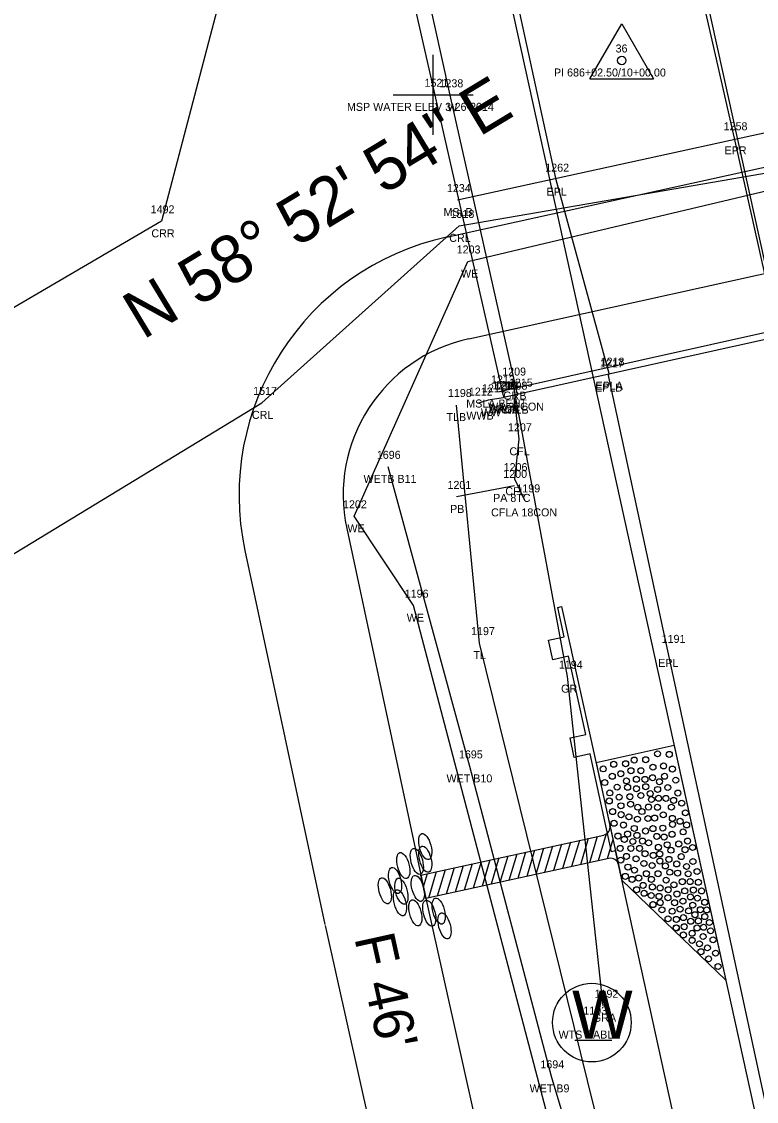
# Model space of a CAD drawing. Extents: x 2521558 to 2525396, y 882711 to 887632.
# Drawn here: x 2523714.7 to 2523806.5, y 884989.6 to 885124.5 of the extents above; entities that cross this region are included whole.
import ezdxf

# ---------------------------------------------------------------- set-up
doc = ezdxf.new("R2010")
doc.units = 0
for name, color, linetype in [('RD_EV_JurisArea', 7, 'Continuous'), ('RD_EX_BldgApp', 7, 'Continuous'), ('RD_EX_BldgApp_txCode', 7, 'Continuous'), ('RD_EX_Bridge', 7, 'Continuous'), ('RD_EX_Bridge_txCode', 7, 'Continuous'), ('RD_EX_Conc', 7, 'Continuous'), ('RD_EX_Conc_txCode', 7, 'Continuous'), ('RD_EX_DR_Pipe', 7, 'Continuous'), ('RD_EX_DR_Pipe_txCode', 7, 'Continuous'), ('RD_EX_GuardRail', 7, 'Continuous'), ('RD_EX_GuardRail_txCode', 7, 'Continuous'), ('RD_EX_H2O', 7, 'Continuous'), ('RD_EX_H2O_txCode', 7, 'Continuous'), ('RD_EX_H2O_WetLd_txCode', 7, 'Continuous'), ('RD_EX_Misc', 7, 'Continuous'), ('RD_EX_Misc_txCode', 7, 'Continuous'), ('RD_EX_Road', 7, 'Continuous'), ('RD_EX_Road_txCode', 7, 'Continuous'), ('RD_EX_UT', 7, 'Continuous'), ('RD_EX_UT_txCode', 7, 'Continuous'), ('RD_EX_VEG', 7, 'Continuous'), ('RD_EX_VEG_txCode', 7, 'Continuous'), ('RD_HC_Data', 7, 'Continuous'), ('RD_HC_txCode', 7, 'Continuous'), ('RD_PD_Bridge', 7, 'Continuous'), ('RD_PD_CstnLmt', 7, 'Continuous'), ('RD_PD_DR_ErosCtrl', 7, 'Continuous'), ('RD_PD_Final_TrvlWay', 7, 'Continuous'), ('RD_PD_GR', 7, 'Continuous'), ('RD_PD_PaveShd', 7, 'Continuous'), ('RD_SMD_Locator', 7, 'Continuous')]:
    doc.layers.add(name, color=color, linetype=linetype)

# ---------------------------------------------------------------- blocks, each defined once
blk = doc.blocks.new('TBC1')
at = {"layer": 'RD_PD_GR'}
blk.add_lwpolyline([(12.5, 2.5), (15, 2.5), (15, 0.49), (25, 0.49), (25, 2.5), (27.5, 2.5), (27.5, 0.49), (31.25, 0.49), (31.25, 0), (0, 0), (0, 0.49), (12.5, 0.49)], close=True, dxfattribs=at)

msp = doc.modelspace()

# ---------------------------------------------------------------- linework, layer by layer
at = {"layer": 'RD_EV_JurisArea'}
msp.add_lwpolyline([(2523827.75, 884469.64), (2523867.43, 884517.67), (2523885.95, 884534.84), (2523882.77, 884582.72), (2523847.74, 884736.42), (2523822.93, 884833.79), (2523804.26, 884914.89), (2523780.91, 884992.76), (2523770.73, 885031.48), (2523760.5, 885068.9)], dxfattribs=at)
at = {"layer": 'RD_EX_BldgApp'}
msp.add_lwpolyline([(2523776.68, 885077.92), (2523768.27, 885115.31), (2523760.2, 885151.9)], dxfattribs=at)
at = {"layer": 'RD_EX_Bridge'}
for points in [[(2523774.91, 885077.6), (2523821.2, 885087.83), (2523805.06, 885161.89), (2523758.15, 885151.44), (2523774.91, 885077.6)], [(2523774.9, 885077.54), (2523773.02, 885077.21), (2523771.67, 885076.8)]]:
    msp.add_lwpolyline(points, dxfattribs=at)
at = {"layer": 'RD_EX_Conc'}
msp.add_lwpolyline([(2523777.61, 885064.71), (2523776.36, 885067.36), (2523776.88, 885072.34), (2523776.32, 885077.54)], dxfattribs=at)
at = {"layer": 'RD_EX_DR_Pipe'}
msp.add_line((2523776.32, 885066.52), (2523769.04, 885065.14), dxfattribs=at)
at = {"layer": 'RD_EX_GuardRail'}
msp.add_lwpolyline([(2523787.38, 885001.58), (2523782.91, 885042.69), (2523776.15, 885079.3)], dxfattribs=at)
at = {"layer": 'RD_EX_H2O'}
for points in [[(2523582.82, 884766.34), (2523598.11, 884856.98), (2523627.59, 884901.75), (2523623.76, 884928.28), (2523586.58, 884955.43), (2523600.94, 884974.12), (2523633.05, 884997.68), (2523679.17, 885037.05), (2523744.72, 885076.89), (2523769.38, 885099), (2523825.47, 885108.66), (2523825.47, 885108.66), (2523845.24, 885110.83), (2523890.25, 885154.93)], [(2523741.75, 885135.92), (2523732.18, 885099.57), (2523664.9, 885060.26), (2523614.86, 885022.02), (2523558.95, 884972.63), (2523560.62, 884942.42), (2523490.01, 884911.76)], [(2523792.73, 884941.12), (2523763.67, 885051.56), (2523756.26, 885062.72), (2523770.47, 885094.55), (2523817.57, 885105.71), (2523827.83, 885106)]]:
    msp.add_lwpolyline(points, dxfattribs=at)
at = {"layer": 'RD_EX_Misc'}
for p, q in [((2523766.13, 885110.37), (2523766.13, 885120.37)), ((2523761.13, 885115.37), (2523771.13, 885115.37)), ((2523816.08, 885112.47), (2523769.2, 885102.22)), ((2523774.43, 885078.31), (2523821.35, 885088.78))]:
    msp.add_line(p, q, dxfattribs=at)
at = {"layer": 'RD_EX_Road'}
for p, q in [((2523803.79, 885109.94), (2523798.3, 885134.14)), ((2523781.52, 885104.77), (2523776.18, 885129.21)), ((2523809.32, 885085.19), (2523803.79, 885109.94)), ((2523788.14, 885080.54), (2523781.52, 885104.77)), ((2523788.05, 885080.31), (2523788.14, 885080.54)), ((2523795.47, 885045.91), (2523788.05, 885080.31)), ((2523817, 884946.3), (2523795.47, 885045.91))]:
    msp.add_line(p, q, dxfattribs=at)
at = {"layer": 'RD_EX_UT'}
msp.add_line((2523783.84, 884997.27), (2523788.47, 884997.27), dxfattribs=at)
msp.add_circle((2523785.97, 884999.48), 4.91, dxfattribs=at)
at = {"layer": 'RD_EX_VEG'}
msp.add_lwpolyline([(2523800.23, 884418.22), (2523892.24, 884498.97), (2523844.57, 884752.81), (2523771.94, 885046.88), (2523769.06, 885076.62)], dxfattribs=at)
at = {"layer": 'RD_HC_Data'}
for p, q in [((2523785.73, 885117.37), (2523789.7, 885124.25)), ((2523789.7, 885124.25), (2523793.67, 885117.37)), ((2523785.73, 885117.37), (2523793.67, 885117.37))]:
    msp.add_line(p, q, dxfattribs=at)
msp.add_circle((2523789.7, 885119.66), 0.529, dxfattribs=at)
at = {"layer": 'RD_PD_CstnLmt'}
for p, q in [((2523755.34, 885061.18), (2523765.33, 885014.45)), ((2523765.33, 885014.45), (2523787.17, 884916.87))]:
    msp.add_line(p, q, dxfattribs=at)
msp.add_lwpolyline([(2523770.59, 885084.9), (2523821.14, 885096.03)], dxfattribs=at)
msp.add_arc((2523774.89, 885065.36), 20, 102.4185, 192.0677, dxfattribs=at)
at = {"layer": 'RD_PD_DR_ErosCtrl'}
for p, q in [((2523742.62, 885058.46), (2523752.61, 885011.74)), ((2523752.64, 885011.61), (2523774.49, 884914.03))]:
    msp.add_line(p, q, dxfattribs=at)
msp.add_lwpolyline([(2523767.8, 885097.59), (2523818.34, 885108.72)], dxfattribs=at)
msp.add_arc((2523774.89, 885065.36), 33, 102.4185, 192.0677, dxfattribs=at)
at = {"layer": 'RD_PD_Final_TrvlWay'}
for p, q in [((2523720.24, 885490.91), (2524037.44, 884050.42)), ((2523696.8, 885485.75), (2524014, 884045.26))]:
    msp.add_line(p, q, dxfattribs=at)
at = {"layer": 'RD_PD_GR'}
msp.add_line((2523896.44, 884532.63), (2523788.91, 885020.93), dxfattribs=at)
at = {"layer": 'RD_PD_PaveShd'}
for p, q in [((2523796.26, 885034.07), (2523786.49, 885031.92)), ((2523796.26, 885034.07), (2523802.71, 885004.77)), ((2523786.49, 885031.92), (2523788.43, 885023.13)), ((2523764.59, 885017.89), (2523787.45, 885022.91)), ((2523784.41, 885022.24), (2523783.42, 885018.96)), ((2523784.41, 885022.24), (2523783.42, 885018.96)), ((2523785.52, 885022.49), (2523784.54, 885019.2)), ((2523785.52, 885022.49), (2523784.54, 885019.2)), ((2523786.64, 885022.74), (2523785.66, 885019.45)), ((2523786.64, 885022.74), (2523785.66, 885019.45)), ((2523787.78, 885023.05), (2523786.77, 885019.69)), ((2523788.61, 885022.33), (2523787.89, 885019.94)), ((2523788.43, 885023.13), (2523789.08, 885020.2)), ((2523777.7, 885020.77), (2523776.72, 885017.48)), ((2523777.7, 885020.77), (2523776.72, 885017.48)), ((2523778.82, 885021.02), (2523777.83, 885017.73)), ((2523778.82, 885021.02), (2523777.83, 885017.73)), ((2523779.94, 885021.26), (2523778.95, 885017.98)), ((2523779.94, 885021.26), (2523778.95, 885017.98)), ((2523781.05, 885021.51), (2523780.07, 885018.22)), ((2523781.05, 885021.51), (2523780.07, 885018.22)), ((2523782.17, 885021.75), (2523781.19, 885018.47)), ((2523782.17, 885021.75), (2523781.19, 885018.47)), ((2523783.29, 885022), (2523782.3, 885018.71)), ((2523788.1, 885019.98), (2523765.22, 885014.96)), ((2523772.12, 885019.55), (2523771.13, 885016.26)), ((2523772.12, 885019.55), (2523771.13, 885016.26)), ((2523773.23, 885019.79), (2523772.25, 885016.5)), ((2523773.23, 885019.79), (2523772.37, 885016.91)), ((2523774.35, 885020.04), (2523773.37, 885016.75)), ((2523774.35, 885020.04), (2523773.37, 885016.75)), ((2523775.47, 885020.28), (2523774.48, 885016.99)), ((2523775.47, 885020.28), (2523774.48, 885016.99)), ((2523776.58, 885020.53), (2523775.6, 885017.24)), ((2523776.58, 885020.53), (2523775.6, 885017.24)), ((2523789.08, 885020.2), (2523789.72, 885017.27)), ((2523765.41, 885018.07), (2523764.91, 885016.4)), ((2523766.53, 885018.32), (2523765.54, 885015.03)), ((2523766.53, 885018.32), (2523765.67, 885015.44)), ((2523767.65, 885018.56), (2523766.66, 885015.28)), ((2523767.65, 885018.56), (2523766.66, 885015.28)), ((2523768.76, 885018.81), (2523767.78, 885015.52)), ((2523768.76, 885018.81), (2523767.78, 885015.52)), ((2523769.88, 885019.05), (2523768.9, 885015.77)), ((2523769.88, 885019.05), (2523768.9, 885015.77)), ((2523771, 885019.3), (2523770.01, 885016.01)), ((2523771, 885019.3), (2523770.01, 885016.01)), ((2523765.22, 885014.96), (2523764.59, 885017.89)), ((2523802.71, 885004.77), (2523789.72, 885017.27))]:
    msp.add_line(p, q, dxfattribs=at)
for centre in [(2523794.18, 885033.05), (2523794.18, 885033.05), (2523795.65, 885032.98), (2523795.65, 885032.98), (2523788.7, 885031.75), (2523788.7, 885031.75), (2523790.19, 885031.82), (2523790.19, 885031.82), (2523791.26, 885032.27), (2523791.26, 885032.27), (2523792.7, 885032.31), (2523792.7, 885032.31), (2523793.61, 885031.38), (2523793.61, 885031.38), (2523794.93, 885031.54), (2523794.93, 885031.54), (2523787.39, 885031.17), (2523787.39, 885031.17), (2523787.39, 885031.17), (2523788.52, 885030.25), (2523788.52, 885030.25), (2523789.59, 885030.57), (2523789.59, 885030.57), (2523790.86, 885030.94), (2523790.86, 885030.94), (2523791.53, 885029.87), (2523791.53, 885029.87), (2523792.1, 885030.94), (2523792.1, 885030.94), (2523792.61, 885029.86), (2523792.61, 885029.86), (2523793.55, 885030.07), (2523793.55, 885030.07), (2523795.05, 885030.24), (2523795.05, 885030.24), (2523796.03, 885031.15), (2523796.03, 885031.15), (2523787.58, 885029.46), (2523787.58, 885029.46), (2523789.13, 885028.89), (2523789.13, 885028.89), (2523790.3, 885029.67), (2523790.3, 885029.67), (2523790.44, 885028.87), (2523790.44, 885028.87), (2523791.55, 885028.69), (2523791.55, 885028.69), (2523792.7, 885028.94), (2523792.7, 885028.94), (2523794.19, 885028.6), (2523794.19, 885028.6), (2523794.42, 885029.57), (2523794.42, 885029.57), (2523795.46, 885028.84), (2523795.46, 885028.84), (2523796.46, 885029.76), (2523796.46, 885029.76), (2523788.15, 885027.16), (2523788.15, 885027.16), (2523788.21, 885028.17), (2523788.21, 885028.17), (2523789.38, 885027.64), (2523789.38, 885027.64), (2523790.72, 885027.69), (2523790.72, 885027.69), (2523792.1, 885027.84), (2523792.1, 885027.84), (2523793.26, 885028.08), (2523793.42, 885027.34), (2523793.42, 885027.34), (2523794.3, 885027.5), (2523794.3, 885027.5), (2523795.22, 885027.48), (2523795.22, 885027.48), (2523796.19, 885027.24), (2523796.19, 885027.24), (2523796.72, 885028.15), (2523796.72, 885028.15), (2523788.57, 885025.83), (2523788.57, 885025.83), (2523789.61, 885026.56), (2523789.61, 885026.56), (2523790.81, 885026.76), (2523790.81, 885026.76), (2523791.71, 885026.38), (2523791.71, 885026.38), (2523792.23, 885025.84), (2523792.23, 885025.84), (2523793.05, 885026.4), (2523793.05, 885026.4), (2523794.17, 885026.37), (2523794.17, 885026.37), (2523795.91, 885026.39), (2523795.91, 885026.39), (2523797.2, 885026.89), (2523797.2, 885026.89), (2523789.63, 885025.45), (2523789.63, 885025.45), (2523790.61, 885025.18), (2523790.61, 885025.18), (2523791.66, 885024.89), (2523791.66, 885024.89), (2523792.98, 885024.97), (2523792.98, 885024.97), (2523793.81, 885025.03), (2523793.81, 885025.03), (2523794.9, 885025.43), (2523794.9, 885025.43), (2523796.03, 885024.99), (2523796.03, 885024.99), (2523796.99, 885024.62), (2523796.99, 885024.62), (2523797.66, 885025.68), (2523797.66, 885025.68), (2523788.75, 885024.37), (2523788.75, 885024.37), (2523789.92, 885024.15), (2523789.92, 885024.15), (2523791.27, 885023.73), (2523791.27, 885023.73), (2523792.68, 885023.41), (2523792.68, 885023.41), (2523793.6, 885023.71), (2523793.6, 885023.71), (2523794.84, 885023.77), (2523794.84, 885023.77), (2523796.05, 885024.24), (2523796.05, 885024.24), (2523797.38, 885023.3), (2523797.38, 885023.3), (2523797.81, 885024.16), (2523789.23, 885022.78), (2523789.23, 885022.78), (2523790.03, 885022.36), (2523790.03, 885022.36), (2523790.44, 885023.03), (2523790.44, 885023.03), (2523791.09, 885022.1), (2523791.09, 885022.1), (2523791.61, 885022.86), (2523791.61, 885022.86), (2523792.3, 885022.15), (2523792.3, 885022.15), (2523793.06, 885021.93), (2523793.06, 885021.93), (2523794.09, 885022.74), (2523794.09, 885022.74), (2523795, 885022.65), (2523795, 885022.65), (2523795.99, 885023), (2523795.99, 885023), (2523796.83, 885021.79), (2523796.83, 885021.79), (2523797.93, 885022.16), (2523797.93, 885022.16), (2523789.51, 885021.24), (2523789.51, 885021.24), (2523790.85, 885021.23), (2523790.85, 885021.23), (2523791.93, 885021.24), (2523791.93, 885021.24), (2523792.62, 885020.57), (2523792.62, 885020.57), (2523794.28, 885021.38), (2523794.28, 885021.38), (2523794.45, 885020.54), (2523794.45, 885020.54), (2523795.39, 885021.69), (2523795.39, 885021.69), (2523795.85, 885021.01), (2523795.85, 885021.01), (2523797.62, 885021.07), (2523797.62, 885021.07), (2523798.56, 885021.35), (2523798.56, 885021.35), (2523789.58, 885019.77), (2523789.58, 885019.77), (2523790.3, 885020.24), (2523790.3, 885020.24), (2523791.49, 885019.93), (2523791.49, 885019.93), (2523792.48, 885019.35), (2523792.48, 885019.35), (2523793.5, 885019.1), (2523793.5, 885019.1), (2523793.65, 885020.36), (2523793.65, 885020.36), (2523794.47, 885019.66), (2523794.47, 885019.66), (2523795.16, 885019.05), (2523795.16, 885019.05), (2523795.61, 885019.86), (2523795.61, 885019.86), (2523796.58, 885019.29), (2523796.58, 885019.29), (2523797.14, 885020.21), (2523797.14, 885020.21), (2523798.61, 885019.6), (2523798.61, 885019.6), (2523790.16, 885017.74), (2523790.16, 885017.74), (2523790.16, 885017.74), (2523790.48, 885018.9), (2523790.48, 885018.9), (2523791.3, 885018.52), (2523791.3, 885018.52), (2523792.78, 885018.07), (2523792.78, 885018.07), (2523794.24, 885018.07), (2523794.24, 885018.07), (2523795.71, 885018.26), (2523795.71, 885018.26), (2523796.69, 885018.15), (2523796.69, 885018.15), (2523797.8, 885018.98), (2523797.8, 885018.98), (2523798.01, 885018.06), (2523798.01, 885018.06), (2523799.12, 885018.35), (2523799.12, 885018.35), (2523790.99, 885017.37), (2523790.99, 885017.37), (2523791.83, 885017.53), (2523791.83, 885017.53), (2523792.38, 885016.62), (2523792.38, 885016.62), (2523793.41, 885017.37), (2523793.41, 885017.37), (2523793.54, 885016.42), (2523793.54, 885016.42), (2523795.25, 885017.27), (2523795.25, 885017.27), (2523796.23, 885016.69), (2523796.23, 885016.69), (2523797.27, 885017.07), (2523797.27, 885017.07), (2523798.25, 885017.09), (2523798.25, 885017.09), (2523799.28, 885017), (2523799.28, 885017), (2523791.56, 885016.08), (2523791.56, 885016.08), (2523792.5, 885015.63), (2523792.5, 885015.63), (2523793.39, 885015.35), (2523793.39, 885015.35), (2523794.37, 885015.24), (2523794.37, 885015.24), (2523794.5, 885016.3), (2523794.5, 885016.3), (2523795.48, 885015.07), (2523795.48, 885015.07), (2523795.51, 885016.08), (2523795.51, 885016.08), (2523796.6, 885015.53), (2523796.6, 885015.53), (2523797.58, 885015.93), (2523797.58, 885015.93), (2523798.29, 885015.17), (2523798.29, 885015.17), (2523798.66, 885016.03), (2523798.66, 885016.03), (2523799.17, 885015.02), (2523799.17, 885015.02), (2523799.68, 885015.92), (2523799.68, 885015.92), (2523793.61, 885014.22), (2523793.62, 885014.21), (2523794.51, 885014.46), (2523794.51, 885014.46), (2523796.31, 885014.45), (2523796.31, 885014.45), (2523796.99, 885013.65), (2523796.99, 885013.65), (2523797.35, 885014.64), (2523797.35, 885014.64), (2523798.57, 885014.14), (2523798.57, 885014.14), (2523800.08, 885014.5), (2523800.08, 885014.5), (2523794.73, 885013.56), (2523794.73, 885013.56), (2523795.49, 885012.44), (2523795.49, 885012.44), (2523796.01, 885013.39), (2523796.01, 885013.39), (2523796.54, 885012.37), (2523796.54, 885012.37), (2523797.42, 885012.59), (2523797.42, 885012.59), (2523798.06, 885013.43), (2523798.06, 885013.43), (2523798.86, 885012.95), (2523798.86, 885012.95), (2523799.53, 885013.58), (2523799.53, 885013.58), (2523800.07, 885012.71), (2523800.07, 885012.71), (2523800.32, 885013.55), (2523800.32, 885013.55), (2523796.5, 885011.32), (2523796.52, 885011.3), (2523797.51, 885011.45), (2523797.51, 885011.45), (2523798.32, 885012.13), (2523798.32, 885012.13), (2523799.12, 885011.3), (2523799.12, 885011.3), (2523799.28, 885012.18), (2523799.28, 885012.18), (2523799.93, 885011.38), (2523799.93, 885011.38), (2523800.66, 885011.98), (2523800.66, 885011.98), (2523797.41, 885010.43), (2523797.41, 885010.43), (2523798.5, 885010.63), (2523798.5, 885010.63), (2523798.5, 885009.75), (2523799.88, 885010.23), (2523799.88, 885010.23), (2523800.8, 885010.94), (2523800.8, 885010.94), (2523801.12, 885009.82), (2523801.12, 885009.82), (2523799.42, 885009.32), (2523799.42, 885009.32), (2523799.61, 885008.33), (2523799.61, 885008.33), (2523800.42, 885008.81), (2523800.42, 885008.81), (2523800.55, 885007.44), (2523800.55, 885007.44), (2523801.43, 885008.15), (2523801.43, 885008.15), (2523801.74, 885006.48)]:
    msp.add_circle(centre, 0.375, dxfattribs=at)
for centre, start, end in [((2523787.24, 885023.89), 282.3889, 12.4185), ((2523788.31, 885019.01), 12.4185, 102.3889)]:
    msp.add_arc(centre, 1, start, end, dxfattribs=at)
for centre in [(2523765.15, 885021.46), (2523765.15, 885021.46), (2523762.41, 885019.09), (2523762.41, 885019.09), (2523764.1, 885019.62), (2523764.1, 885019.62), (2523765.15, 885019.89), (2523765.15, 885019.89), (2523761.38, 885017.23), (2523761.38, 885017.23), (2523760.1, 885015.94), (2523760.1, 885015.94), (2523762.17, 885015.88), (2523762.17, 885015.88), (2523764.22, 885016.24), (2523764.22, 885016.24), (2523761.99, 885014.44), (2523761.99, 885014.44), (2523763.91, 885013.19), (2523763.91, 885013.19), (2523765.65, 885013.14), (2523765.65, 885013.14), (2523766.83, 885013.41), (2523767.56, 885011.56)]:
    msp.add_ellipse(centre, major_axis=(0.43, -1.62), ratio=0.429445, dxfattribs=at)
at = {"layer": 'RD_SMD_Locator'}
for centre in [(2523789.7, 885119.66), (2523768.27, 885115.31), (2523803.79, 885109.94), (2523781.52, 885104.77), (2523769.2, 885102.22), (2523732.18, 885099.57), (2523769.38, 885099), (2523770.47, 885094.55), (2523788.05, 885080.31), (2523788.14, 885080.54), (2523776.15, 885079.3), (2523774.43, 885078.31), (2523774.9, 885077.54), (2523774.91, 885077.6), (2523774.91, 885077.6), (2523776.32, 885077.54), (2523776.68, 885077.92), (2523744.72, 885076.89), (2523769.06, 885076.62), (2523771.67, 885076.8), (2523773.02, 885077.21), (2523776.88, 885072.34), (2523760.5, 885068.9), (2523776.36, 885067.36), (2523776.32, 885066.52), (2523769.04, 885065.14), (2523777.61, 885064.71), (2523756.26, 885062.72), (2523763.67, 885051.56), (2523771.94, 885046.88), (2523795.47, 885045.91), (2523782.91, 885042.69), (2523770.73, 885031.48), (2523775.33, 885013.36), (2523787.38, 885001.58), (2523780.91, 884992.76)]:
    msp.add_circle(centre, 0.001, dxfattribs=at)

# ---------------------------------------------------------------- block references
at = {"layer": 'RD_PD_Bridge', "rotation": 102.41848259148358}
msp.add_blockref('TBC1', (2523788.91, 885020.93), dxfattribs=at)

# ---------------------------------------------------------------- texts
at = {"layer": 'RD_EX_BldgApp_txCode'}
for s, p in [('1238', (2523766.93, 885116.31)), ('W', (2523767.9, 885113.31)), ('1215', (2523775.61, 885078.92)), ('WA 32CON', (2523773, 885075.92))]:
    msp.add_text(s, height=1, dxfattribs=at).set_placement(p)
at = {"layer": 'RD_EX_Bridge_txCode'}
for s, p in [('1212', (2523770.6, 885077.8)), ('1211', (2523772.24, 885078.21)), ('1246', (2523773.54, 885078.6)), ('1210', (2523773.79, 885078.54)), ('1214', (2523773.84, 885078.6)), ('WW', (2523772.11, 885075.21)), ('BRCA', (2523773.17, 885075.6)), ('BRCB', (2523773.18, 885075.6)), ('WWA', (2523773.5, 885075.54)), ('WWB', (2523770.29, 885074.8))]:
    msp.add_text(s, height=1, dxfattribs=at).set_placement(p)
at = {"layer": 'RD_EX_Conc_txCode'}
for s, p in [('1208', (2523774.94, 885078.54)), ('CFLB', (2523774.65, 885075.54)), ('1207', (2523775.49, 885073.34)), ('CFL', (2523775.67, 885070.34)), ('1206', (2523774.95, 885068.36)), ('1199', (2523776.54, 885065.71)), ('CFL', (2523775.16, 885065.36)), ('CFLA 18CON', (2523773.38, 885062.71))]:
    msp.add_text(s, height=1, dxfattribs=at).set_placement(p)
at = {"layer": 'RD_EX_DR_Pipe_txCode'}
for s, p in [('1200', (2523774.9, 885067.52)), ('1201', (2523767.93, 885066.14)), ('PA 8TC', (2523773.63, 885064.52)), ('PB', (2523768.26, 885063.14))]:
    msp.add_text(s, height=1, dxfattribs=at).set_placement(p)
at = {"layer": 'RD_EX_GuardRail_txCode'}
for s, p in [('1209', (2523774.77, 885080.3)), ('GRB', (2523774.9, 885077.3)), ('1194', (2523781.85, 885043.69)), ('GR', (2523782.13, 885040.69)), ('1192', (2523786.31, 885002.58)), ('GRA', (2523786.11, 884999.58))]:
    msp.add_text(s, height=1, dxfattribs=at).set_placement(p)
at = {"layer": 'RD_EX_H2O_txCode'}
for s, p in [('1492', (2523730.84, 885100.57)), ('1518', (2523768.31, 885100)), ('CRR', (2523730.93, 885097.57)), ('CRL', (2523768.15, 885097)), ('1203', (2523769.08, 885095.55)), ('WE', (2523769.63, 885092.55)), ('1517', (2523743.65, 885077.89)), ('CRL', (2523743.49, 885074.89)), ('1202', (2523754.88, 885063.72)), ('WE', (2523755.43, 885060.72)), ('1196', (2523762.59, 885052.56)), ('WE', (2523762.84, 885049.56))]:
    msp.add_text(s, height=1, dxfattribs=at).set_placement(p)
at = {"layer": 'RD_EX_H2O_WetLd_txCode'}
for s, p in [('1696', (2523759.1, 885069.9)), ('WETB B11', (2523757.44, 885066.9)), ('1695', (2523769.36, 885032.48)), ('WET B10', (2523767.81, 885029.48)), ('1694', (2523779.54, 884993.76)), ('WET B9', (2523778.19, 884990.76))]:
    msp.add_text(s, height=1, dxfattribs=at).set_placement(p)
at = {"layer": 'RD_EX_Misc_txCode'}
for s, p in [('1521', (2523765.06, 885116.37)), ('MSP WATER ELEV 3-26-2014', (2523755.37, 885113.37)), ('1234', (2523767.86, 885103.22)), ('MSLB', (2523767.44, 885100.22)), ('1213', (2523773.37, 885079.31)), ('MSLA BENT', (2523770.28, 885076.31))]:
    msp.add_text(s, height=1, dxfattribs=at).set_placement(p)
at = {"layer": 'RD_EX_Road_txCode'}
for s, p in [('1258', (2523802.44, 885110.94)), ('EPR', (2523802.56, 885107.94)), ('1262', (2523780.15, 885105.77)), ('EPL', (2523780.31, 885102.77)), ('1217', (2523786.98, 885081.31)), ('1218', (2523787.07, 885081.54)), ('EPLB', (2523786.37, 885078.31)), ('EPLA', (2523786.44, 885078.54)), ('1191', (2523794.69, 885046.91)), ('EPL', (2523794.26, 885043.91))]:
    msp.add_text(s, height=1, dxfattribs=at).set_placement(p)
at = {"layer": 'RD_EX_UT'}
msp.add_text('W', height=6, dxfattribs=at).set_placement((2523783.5, 884997.48))
at = {"layer": 'RD_EX_UT_txCode'}
for s, p in [('1193', (2523784.91, 885000.48)), ('WTS CABLE', (2523781.81, 884997.48))]:
    msp.add_text(s, height=1, dxfattribs=at).set_placement(p)
at = {"layer": 'RD_EX_VEG_txCode'}
for s, p in [('1198', (2523767.99, 885077.62)), ('TLB', (2523767.81, 885074.62)), ('1197', (2523770.88, 885047.88)), ('TL', (2523771.17, 885044.88))]:
    msp.add_text(s, height=1, dxfattribs=at).set_placement(p)
at = {"layer": 'RD_HC_Data'}
msp.add_text('N 58%%d 52\' 54" E', height=6, rotation=31.1184, dxfattribs=at).set_placement((2523729.87, 885084.71))
at = {"layer": 'RD_HC_txCode'}
for s, p in [('36', (2523788.94, 885120.66)), ('PI 686+02.50/10+00.00', (2523781.24, 885117.66))]:
    msp.add_text(s, height=1, dxfattribs=at).set_placement(p)
at = {"layer": 'RD_PD_CstnLmt'}
msp.add_text("F 46'", height=5, rotation=282.4185, dxfattribs=at).set_placement((2523756.27, 885010.08))

doc.saveas('drawing.dxf')
